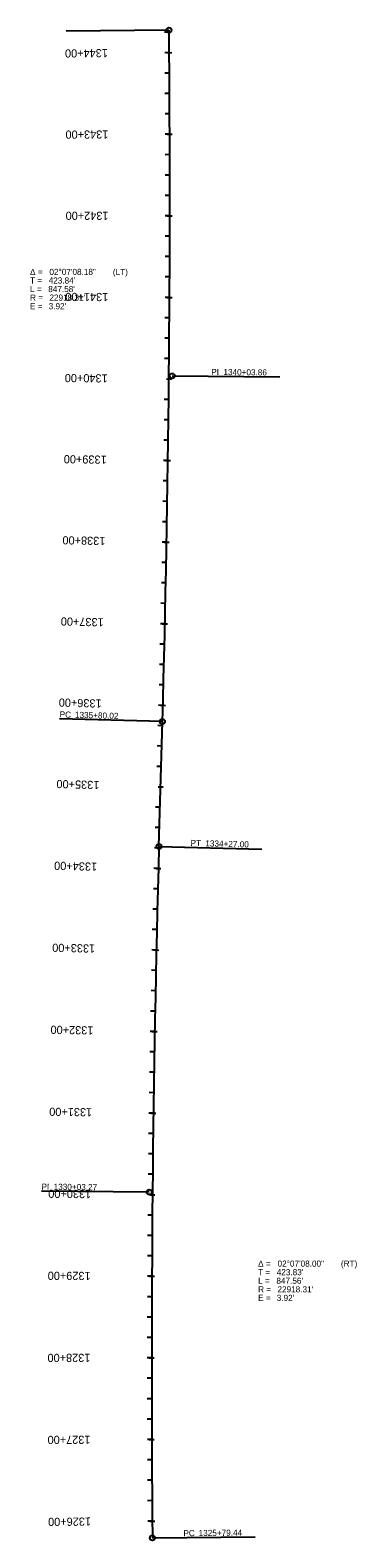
# Model space of a CAD drawing. Extents: x 19548215 to 19548727, y 7547983 to 7562114.
# Drawn here: x 19548215 to 19548615, y 7554578 to 7556426 of the extents above; entities that cross this region are included whole.
import ezdxf

# ---------------------------------------------------------------- set-up
doc = ezdxf.new("R2010")
doc.units = 0
for name, color, linetype in [('Contours Major', 7, 'Continuous'), ('Contours Minor', 7, 'Continuous'), ('Default', 7, 'Continuous'), ('TextAlignment', 7, 'Continuous'), ('TextAlignmentSml', 7, 'Continuous')]:
    doc.layers.add(name, color=color, linetype=linetype)

msp = doc.modelspace()

# ---------------------------------------------------------------- linework, layer by layer
at = {"layer": 'Contours Major'}
for p, q in [((19548385.4, 7556398.8), (19548379.9, 7556398.7)), ((19548385.9, 7556298.8), (19548380.5, 7556298.7)), ((19548386.1, 7556198.8), (19548380.6, 7556198.8)), ((19548385.8, 7556098.8), (19548380.3, 7556098.8)), ((19548381.9, 7555998.8), (19548388.1, 7555998.7)), ((19548383.8, 7555898.8), (19548378.4, 7555898.8)), ((19548382.2, 7555798.8), (19548376.7, 7555798.9)), ((19548380.1, 7555698.8), (19548374.7, 7555698.9)), ((19548377.7, 7555598.8), (19548372.2, 7555599)), ((19548371.8, 7555499), (19548377.9, 7555498.8)), ((19548372.1, 7555398.9), (19548366.6, 7555399.1)), ((19548369.6, 7555298.9), (19548364.2, 7555299.1)), ((19548367.6, 7555199), (19548362.1, 7555199.1)), ((19548366, 7555099), (19548360.6, 7555099)), ((19548361.8, 7554999), (19548367.9, 7554999)), ((19548364.1, 7554899), (19548358.7, 7554899)), ((19548363.9, 7554799), (19548358.4, 7554799)), ((19548364, 7554699), (19548358.6, 7554699)), ((19548364.6, 7554599), (19548359.2, 7554598.9))]:
    msp.add_line(p, q, dxfattribs=at)
at = {"layer": 'Contours Minor'}
msp.add_line((19548372.8, 7555425.9), (19548377.1, 7555578.9), dxfattribs=at)
for centre, start, end in [((19525467.8, 7556219.8), 358.39745, 0.51639), ((19571282.2, 7554785), 178.39745, 180.51634)]:
    msp.add_arc(centre, 22918.3, start, end, dxfattribs=at)
at = {"layer": 'Default'}
msp.add_line((19548372.8, 7555425.9), (19548377.1, 7555578.9), dxfattribs=at)
for centre, start, end in [((19525467.8, 7556219.8), 358.39745, 0.51639), ((19571282.2, 7554785), 178.39745, 180.51634)]:
    msp.add_arc(centre, 22918.3, start, end, dxfattribs=at)
at = {"layer": 'TextAlignment'}
for p, q in [((19548385.1, 7556426.3), (19548259.1, 7556425.2)), ((19548259.1, 7556425.2), (19548259.1, 7556425.2)), ((19548389, 7556002.5), (19548521, 7556001.3)), ((19548521, 7556001.3), (19548521, 7556001.3)), ((19548377.1, 7555578.9), (19548251.2, 7555582.4)), ((19548251.2, 7555582.4), (19548251.2, 7555582.4)), ((19548372.8, 7555425.9), (19548498.8, 7555422.4)), ((19548498.8, 7555422.4), (19548498.8, 7555422.4)), ((19548361, 7555002.2), (19548229, 7555003.5)), ((19548229, 7555003.5), (19548229, 7555003.5)), ((19548364.8, 7554578.4), (19548490.8, 7554579.6)), ((19548490.8, 7554579.6), (19548490.8, 7554579.6))]:
    msp.add_line(p, q, dxfattribs=at)
for centre in [(19548385.1, 7556426.3), (19548389, 7556002.5), (19548377.1, 7555578.9), (19548372.8, 7555425.9), (19548361, 7555002.2), (19548364.8, 7554578.4)]:
    msp.add_circle(centre, 3.12, dxfattribs=at)
at = {"layer": 'TextAlignmentSml'}
for p, q in [((19548385.2, 7556423.8), (19548379.7, 7556423.7)), ((19548382.3, 7556398.7), (19548388.4, 7556398.8)), ((19548385.6, 7556373.8), (19548380.1, 7556373.7)), ((19548385.7, 7556348.8), (19548380.2, 7556348.7)), ((19548385.8, 7556323.8), (19548380.4, 7556323.7)), ((19548382.9, 7556298.7), (19548389, 7556298.8)), ((19548386, 7556273.8), (19548380.5, 7556273.7)), ((19548386.1, 7556248.8), (19548380.6, 7556248.7)), ((19548386.1, 7556223.8), (19548380.6, 7556223.8)), ((19548383, 7556198.8), (19548389.1, 7556198.8)), ((19548386, 7556173.8), (19548380.6, 7556173.8)), ((19548386, 7556148.8), (19548380.5, 7556148.8)), ((19548385.9, 7556123.8), (19548380.4, 7556123.8)), ((19548382.7, 7556098.8), (19548388.8, 7556098.7)), ((19548385.6, 7556073.8), (19548380.1, 7556073.8)), ((19548385.4, 7556048.8), (19548380, 7556048.8)), ((19548385.2, 7556023.8), (19548379.8, 7556023.8)), ((19548381.9, 7555998.8), (19548388.1, 7555998.7)), ((19548384.8, 7555973.8), (19548379.3, 7555973.8)), ((19548384.5, 7555948.8), (19548379, 7555948.8)), ((19548384.2, 7555923.8), (19548378.7, 7555923.8)), ((19548380.8, 7555898.8), (19548386.9, 7555898.7)), ((19548383.5, 7555873.8), (19548378, 7555873.9)), ((19548383.1, 7555848.8), (19548377.6, 7555848.9)), ((19548382.6, 7555823.8), (19548377.2, 7555823.9)), ((19548379.1, 7555798.8), (19548385.3, 7555798.7)), ((19548381.7, 7555773.8), (19548376.3, 7555773.9)), ((19548381.2, 7555748.8), (19548375.8, 7555748.9)), ((19548380.7, 7555723.8), (19548375.2, 7555723.9)), ((19548377.1, 7555698.9), (19548383.2, 7555698.7)), ((19548379.6, 7555673.8), (19548374.1, 7555673.9)), ((19548379, 7555648.8), (19548373.5, 7555649)), ((19548378.3, 7555623.8), (19548372.9, 7555624)), ((19548374.6, 7555598.9), (19548380.7, 7555598.7)), ((19548377, 7555573.8), (19548371.5, 7555574)), ((19548376.3, 7555548.9), (19548370.8, 7555549)), ((19548375.6, 7555523.9), (19548370.1, 7555524)), ((19548371.8, 7555499), (19548377.9, 7555498.8)), ((19548374.2, 7555473.9), (19548368.7, 7555474)), ((19548373.5, 7555448.9), (19548368, 7555449)), ((19548372.8, 7555423.9), (19548367.3, 7555424.1)), ((19548369, 7555399), (19548375.1, 7555398.8)), ((19548371.4, 7555373.9), (19548366, 7555374.1)), ((19548370.8, 7555348.9), (19548365.3, 7555349.1)), ((19548370.2, 7555323.9), (19548364.7, 7555324.1)), ((19548366.6, 7555299), (19548372.7, 7555298.9)), ((19548369.1, 7555273.9), (19548363.6, 7555274.1)), ((19548368.6, 7555249), (19548363.1, 7555249.1)), ((19548368.1, 7555224), (19548362.6, 7555224.1)), ((19548364.5, 7555199), (19548370.7, 7555198.9)), ((19548367.2, 7555174), (19548361.7, 7555174.1)), ((19548366.8, 7555149), (19548361.3, 7555149.1)), ((19548366.4, 7555124), (19548360.9, 7555124.1)), ((19548363, 7555099), (19548369.1, 7555098.9)), ((19548365.7, 7555074), (19548360.2, 7555074)), ((19548365.4, 7555049), (19548359.9, 7555049)), ((19548365.1, 7555024), (19548359.7, 7555024)), ((19548361.8, 7554999), (19548367.9, 7554999)), ((19548364.6, 7554974), (19548359.2, 7554974)), ((19548364.5, 7554949), (19548359, 7554949)), ((19548364.3, 7554924), (19548358.8, 7554924)), ((19548361.1, 7554899), (19548367.2, 7554899)), ((19548364, 7554874), (19548358.6, 7554874)), ((19548364, 7554849), (19548358.5, 7554849)), ((19548363.9, 7554824), (19548358.4, 7554824)), ((19548360.8, 7554799), (19548366.9, 7554799)), ((19548363.9, 7554774), (19548358.4, 7554774)), ((19548363.9, 7554749), (19548358.4, 7554749)), ((19548363.9, 7554724), (19548358.5, 7554724)), ((19548361, 7554699), (19548367.1, 7554699)), ((19548364.1, 7554674), (19548358.7, 7554674)), ((19548364.3, 7554649), (19548358.8, 7554649)), ((19548364.4, 7554624), (19548359, 7554623.9)), ((19548361.6, 7554599), (19548367.7, 7554599))]:
    msp.add_line(p, q, dxfattribs=at)

# ---------------------------------------------------------------- texts
at = {"layer": 'Contours Major'}
for s, rotation, p in [('1340+00', 179.4474, (19548310.1, 7556004.5)), ('1335+00', 178.3975, (19548300, 7555506)), ('1330+00', 179.465, (19548289.9, 7555004.7))]:
    msp.add_text(s, height=10.02, rotation=rotation, dxfattribs=at).set_placement(p)
at = {"layer": 'TextAlignment'}
for s, p in [('T = ', (19548215, 7556115.8)), ('Δ = ', (19548215, 7556126.3)), ("423.84'", (19548237.8, 7556115.8)), ('02°07\'08.18"', (19548238.7, 7556126.3)), (' (LT)', (19548313.6, 7556126.3)), ('L = ', (19548215, 7556105.3)), ("847.58'", (19548237.3, 7556105.3)), ('R = ', (19548215, 7556094.8)), ('E = ', (19548215, 7556084.3)), ("3.92'", (19548237.8, 7556084.3)), ("22918.31'", (19548238.7, 7556094.8)), ('Δ = ', (19548494.2, 7554910.8)), ('T = ', (19548494.2, 7554900.3)), ("423.83'", (19548517, 7554900.3)), ('02°07\'08.00"', (19548518, 7554910.8)), (' (RT)', (19548592.8, 7554910.8)), ('L = ', (19548494.2, 7554889.8)), ('R = ', (19548494.2, 7554879.3)), ("847.56'", (19548516.6, 7554889.8)), ("22918.31'", (19548517.9, 7554879.3)), ('E = ', (19548494.2, 7554868.8)), ("3.92'", (19548517, 7554868.8))]:
    msp.add_text(s, height=7.5, dxfattribs=at).set_placement(p)
for s, rotation, p in [('PI ', 359.4569, (19548436.8, 7556003.7)), ('1340+03.86', 359.4569, (19548451.7, 7556003.6)), ('PC', 358.3975, (19548251.2, 7555584)), ('1335+80.02', 358.3975, (19548269.9, 7555583.5)), ('PT', 358.3975, (19548411.4, 7555426.5)), ('1334+27.00', 358.3975, (19548429.5, 7555426)), ('PI ', 359.4569, (19548229, 7555005.1)), ('1330+03.27', 359.4569, (19548243.9, 7555005)), ('PC', 0.5163, (19548402.8, 7554580.4)), ('1325+79.44', 0.5163, (19548421.4, 7554580.6))]:
    msp.add_text(s, height=7.5, rotation=rotation, dxfattribs=at).set_placement(p)
at = {"layer": 'TextAlignmentSml'}
for s, rotation, p in [('1344+00', 180.4474, (19548310.3, 7556403.2)), ('1343+00', 180.1974, (19548310.9, 7556303.5)), ('1342+00', 179.9474, (19548311.1, 7556203.8)), ('1341+00', 179.6974, (19548310.8, 7556104.2)), ('1340+00', 179.4474, (19548310.1, 7556004.5)), ('1339+00', 179.1974, (19548308.9, 7555904.8)), ('1338+00', 178.9474, (19548307.3, 7555805.2)), ('1337+00', 178.6974, (19548305.3, 7555705.5)), ('1336+00', 178.4474, (19548302.8, 7555605.9)), ('1335+00', 178.3975, (19548300, 7555506)), ('1334+00', 178.465, (19548297.2, 7555405.9)), ('1333+00', 178.715, (19548294.8, 7555305.6)), ('1332+00', 178.965, (19548292.7, 7555205.3)), ('1331+00', 179.215, (19548291.1, 7555105)), ('1330+00', 179.465, (19548289.9, 7555004.7)), ('1329+00', 179.715, (19548289.2, 7554904.4)), ('1328+00', 179.965, (19548288.9, 7554804)), ('1327+00', 180.215, (19548289, 7554703.7)), ('1326+00', 180.465, (19548289.6, 7554603.4))]:
    msp.add_text(s, height=10.02, rotation=rotation, dxfattribs=at).set_placement(p)

doc.saveas('drawing.dxf')
